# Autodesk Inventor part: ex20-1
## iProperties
Created: 2006-04
Part Number: ex20-1
Document SubType Name: Modeling
Designer: E. MOSS
Project: EVERGREEN VALLEY COLLEGE
Description: PLATE
Authority: MS. TEACHER
Author: E. MOSS
Revision Number: A
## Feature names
1. Extrusion1
2. Hole1
3. Extrusion2
